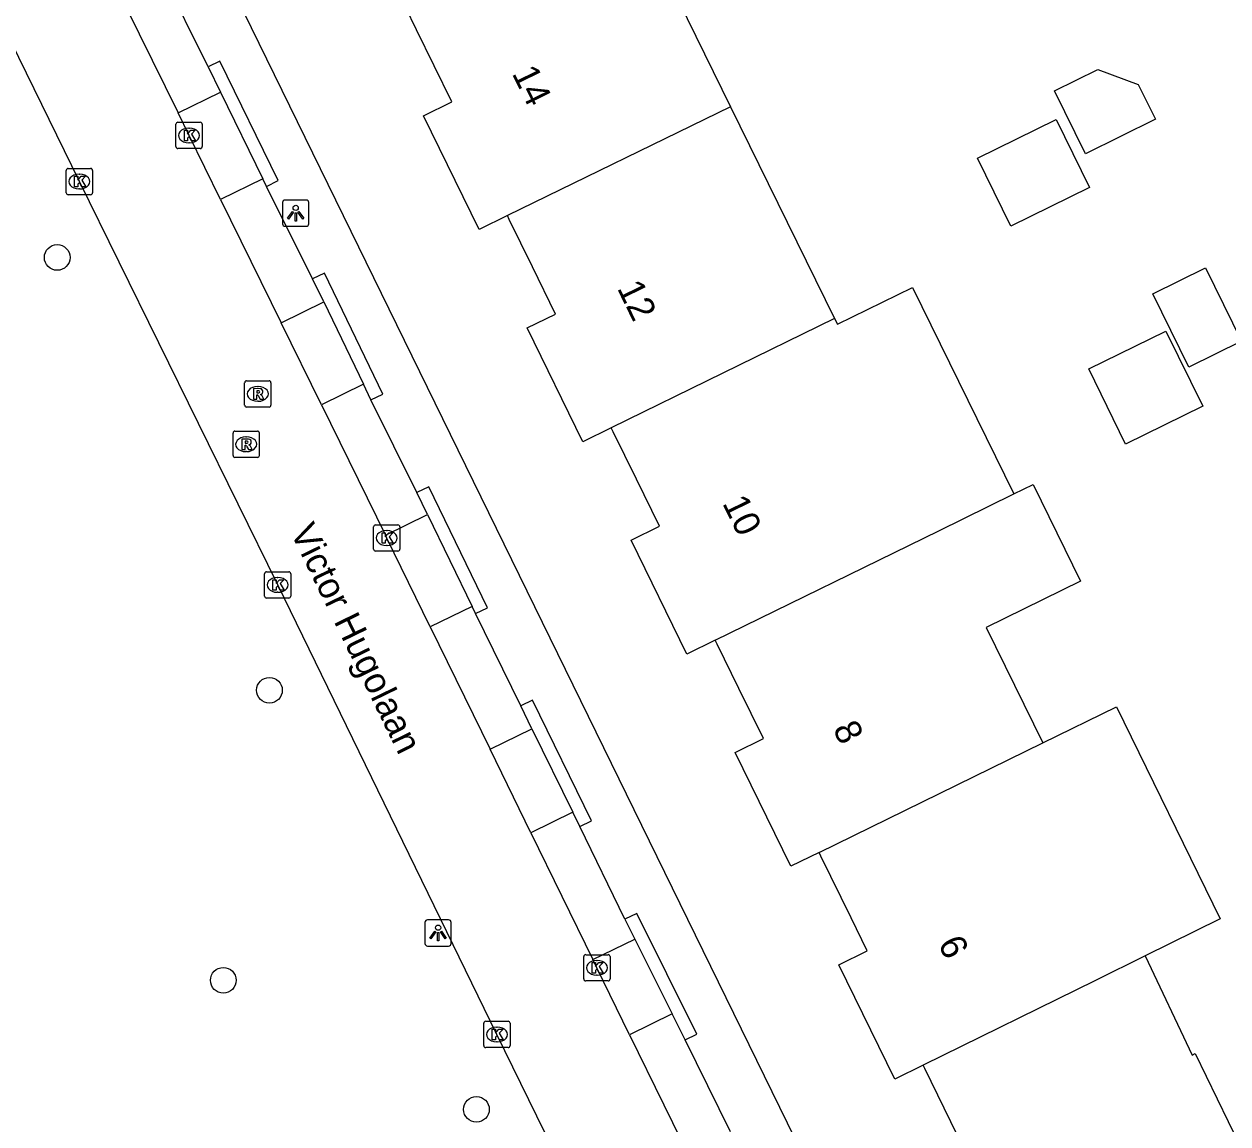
# Model space of a CAD drawing. Extents: x 160457 to 162082, y 388340 to 389736.
# Drawn here: x 160726.81 to 160772.64, y 388685.6 to 388727.48 of the extents above; entities that cross this region are included whole.
import ezdxf

# ---------------------------------------------------------------- set-up
doc = ezdxf.new("R2010")
doc.units = 0
for name, color, linetype in [('IMGEO_Boom', 7, 'Continuous'), ('IMGEO_Kolk', 7, 'Continuous'), ('IMGEO_Lichtpunt', 7, 'Continuous'), ('IMGEO_Openbare_ruimte_label', 7, 'Continuous'), ('IMGEO_Pand', 7, 'Continuous'), ('IMGEO_Pand_nummerreeks', 7, 'Continuous'), ('IMGEO_Parkeervlak_open', 7, 'Continuous'), ('IMGEO_Rijbaan_lokaal_gesloten', 7, 'Continuous'), ('IMGEO_Rioolput', 7, 'Continuous'), ('IMGEO_Voetpad_open', 7, 'Continuous')]:
    doc.layers.add(name, color=color, linetype=linetype)

msp = doc.modelspace()

# ---------------------------------------------------------------- linework, layer by layer
at = {"layer": 'IMGEO_Boom'}
for centre in [(160728.076, 388718.588), (160736.153, 388702.11), (160734.396, 388691.067), (160744.034, 388686.153)]:
    msp.add_circle(centre, 0.489, dxfattribs=at)
at = {"layer": 'IMGEO_Kolk'}
for p, q in [((160732.593, 388722.809), (160732.593, 388723.661)), ((160732.668, 388723.735), (160733.52, 388723.735)), ((160733.081, 388723.515), (160733.106, 388723.515)), ((160733.594, 388723.661), (160733.594, 388722.809)), ((160733.104, 388722.955), (160733.079, 388722.955)), ((160733.52, 388722.735), (160732.668, 388722.735)), ((160728.493, 388721.978), (160729.345, 388721.978)), ((160728.418, 388721.052), (160728.418, 388721.904)), ((160728.906, 388721.758), (160728.931, 388721.758)), ((160729.419, 388721.904), (160729.419, 388721.052)), ((160728.929, 388721.198), (160728.904, 388721.198)), ((160729.345, 388720.978), (160728.493, 388720.978)), ((160740.118, 388707.481), (160740.118, 388708.333)), ((160740.193, 388708.407), (160741.045, 388708.407)), ((160740.606, 388708.187), (160740.631, 388708.187)), ((160741.119, 388708.333), (160741.119, 388707.481)), ((160741.045, 388707.407), (160740.193, 388707.407)), ((160740.629, 388707.627), (160740.604, 388707.627)), ((160735.965, 388705.694), (160735.965, 388706.546)), ((160736.04, 388706.62), (160736.892, 388706.62)), ((160736.453, 388706.4), (160736.478, 388706.4)), ((160736.966, 388706.546), (160736.966, 388705.694)), ((160736.892, 388705.62), (160736.04, 388705.62)), ((160736.476, 388705.84), (160736.451, 388705.84)), ((160748.117, 388691.116), (160748.117, 388691.968)), ((160748.192, 388692.042), (160749.044, 388692.042)), ((160748.605, 388691.822), (160748.63, 388691.822)), ((160749.118, 388691.968), (160749.118, 388691.116)), ((160748.628, 388691.262), (160748.603, 388691.262)), ((160749.044, 388691.042), (160748.192, 388691.042)), ((160744.311, 388688.578), (160744.311, 388689.43)), ((160744.386, 388689.504), (160745.238, 388689.504)), ((160745.312, 388689.43), (160745.312, 388688.578)), ((160744.799, 388689.284), (160744.824, 388689.284)), ((160745.238, 388688.504), (160744.386, 388688.504)), ((160744.822, 388688.724), (160744.797, 388688.724))]:
    msp.add_line(p, q, dxfattribs=at)
for points in [[(160732.593, 388722.809), (160732.593, 388723.661)], [(160732.668, 388723.735), (160733.52, 388723.735)], [(160732.914, 388723.435), (160733.037, 388723.435), (160733.037, 388723.284), (160733.167, 388723.435), (160733.331, 388723.435), (160733.185, 388723.284), (160733.338, 388723.035), (160733.186, 388723.035), (160733.101, 388723.199), (160733.037, 388723.132), (160733.037, 388723.035), (160732.914, 388723.035), (160732.914, 388723.435)], [(160733.594, 388723.661), (160733.594, 388722.809)], [(160733.52, 388722.735), (160732.668, 388722.735)], [(160728.493, 388721.978), (160729.345, 388721.978)], [(160728.418, 388721.052), (160728.418, 388721.904)], [(160728.739, 388721.678), (160728.862, 388721.678), (160728.862, 388721.527), (160728.992, 388721.678), (160729.156, 388721.678), (160729.01, 388721.527), (160729.163, 388721.278), (160729.011, 388721.278), (160728.926, 388721.442), (160728.862, 388721.375), (160728.862, 388721.278), (160728.739, 388721.278), (160728.739, 388721.678)], [(160729.419, 388721.904), (160729.419, 388721.052)], [(160729.345, 388720.978), (160728.493, 388720.978)], [(160740.118, 388707.481), (160740.118, 388708.333)], [(160740.193, 388708.407), (160741.045, 388708.407)], [(160741.119, 388708.333), (160741.119, 388707.481)], [(160740.439, 388708.107), (160740.562, 388708.107), (160740.562, 388707.956), (160740.692, 388708.107), (160740.856, 388708.107), (160740.71, 388707.956), (160740.863, 388707.707), (160740.711, 388707.707), (160740.626, 388707.871), (160740.562, 388707.804), (160740.562, 388707.707), (160740.439, 388707.707), (160740.439, 388708.107)], [(160741.045, 388707.407), (160740.193, 388707.407)], [(160735.965, 388705.694), (160735.965, 388706.546)], [(160736.04, 388706.62), (160736.892, 388706.62)], [(160736.966, 388706.546), (160736.966, 388705.694)], [(160736.286, 388706.32), (160736.409, 388706.32), (160736.409, 388706.169), (160736.539, 388706.32), (160736.703, 388706.32), (160736.557, 388706.169), (160736.71, 388705.92), (160736.558, 388705.92), (160736.473, 388706.084), (160736.409, 388706.017), (160736.409, 388705.92), (160736.286, 388705.92), (160736.286, 388706.32)], [(160736.892, 388705.62), (160736.04, 388705.62)], [(160748.117, 388691.116), (160748.117, 388691.968)], [(160748.192, 388692.042), (160749.044, 388692.042)], [(160748.438, 388691.742), (160748.561, 388691.742), (160748.561, 388691.591), (160748.691, 388691.742), (160748.855, 388691.742), (160748.709, 388691.591), (160748.862, 388691.342), (160748.71, 388691.342), (160748.625, 388691.506), (160748.561, 388691.439), (160748.561, 388691.342), (160748.438, 388691.342), (160748.438, 388691.742)], [(160749.118, 388691.968), (160749.118, 388691.116)], [(160749.044, 388691.042), (160748.192, 388691.042)], [(160744.311, 388688.578), (160744.311, 388689.43)], [(160744.386, 388689.504), (160745.238, 388689.504)], [(160745.312, 388689.43), (160745.312, 388688.578)], [(160744.632, 388689.204), (160744.755, 388689.204), (160744.755, 388689.053), (160744.885, 388689.204), (160745.049, 388689.204), (160744.903, 388689.053), (160745.056, 388688.804), (160744.904, 388688.804), (160744.819, 388688.968), (160744.755, 388688.901), (160744.755, 388688.804), (160744.632, 388688.804), (160744.632, 388689.204)], [(160745.238, 388688.504), (160744.386, 388688.504)]]:
    msp.add_lwpolyline(points, dxfattribs=at)
for centre, start, end in [((160732.67, 388723.659), 91.552, 178.448), ((160732.67, 388723.659), 91.552, 178.448), ((160733.518, 388723.659), 1.552, 88.448), ((160733.518, 388723.659), 1.552, 88.448), ((160732.67, 388722.811), 181.552, 268.448), ((160732.67, 388722.811), 181.552, 268.448), ((160733.518, 388722.811), 271.552, 358.448), ((160733.518, 388722.811), 271.552, 358.448), ((160728.495, 388721.902), 91.552, 178.448), ((160728.495, 388721.902), 91.552, 178.448), ((160729.343, 388721.902), 1.552, 88.448), ((160729.343, 388721.902), 1.552, 88.448), ((160728.495, 388721.054), 181.552, 268.448), ((160728.495, 388721.054), 181.552, 268.448), ((160729.343, 388721.054), 271.552, 358.448), ((160729.343, 388721.054), 271.552, 358.448), ((160740.195, 388708.331), 91.552, 178.448), ((160740.195, 388708.331), 91.552, 178.448), ((160741.043, 388708.331), 1.552, 88.448), ((160741.043, 388708.331), 1.552, 88.448), ((160740.195, 388707.483), 181.552, 268.448), ((160740.195, 388707.483), 181.552, 268.448), ((160741.043, 388707.483), 271.552, 358.448), ((160741.043, 388707.483), 271.552, 358.448), ((160736.042, 388706.544), 91.552, 178.448), ((160736.042, 388706.544), 91.552, 178.448), ((160736.89, 388706.544), 1.552, 88.448), ((160736.89, 388706.544), 1.552, 88.448), ((160736.042, 388705.696), 181.552, 268.448), ((160736.042, 388705.696), 181.552, 268.448), ((160736.89, 388705.696), 271.552, 358.448), ((160736.89, 388705.696), 271.552, 358.448), ((160748.194, 388691.966), 91.552, 178.448), ((160748.194, 388691.966), 91.552, 178.448), ((160749.042, 388691.966), 1.552, 88.448), ((160749.042, 388691.966), 1.552, 88.448), ((160748.194, 388691.118), 181.552, 268.448), ((160748.194, 388691.118), 181.552, 268.448), ((160749.042, 388691.118), 271.552, 358.448), ((160749.042, 388691.118), 271.552, 358.448), ((160744.388, 388689.428), 91.552, 178.448), ((160744.388, 388689.428), 91.552, 178.448), ((160745.236, 388689.428), 1.552, 88.448), ((160745.236, 388689.428), 1.552, 88.448), ((160744.388, 388688.58), 181.552, 268.448), ((160744.388, 388688.58), 181.552, 268.448), ((160745.236, 388688.58), 271.552, 358.448), ((160745.236, 388688.58), 271.552, 358.448)]:
    msp.add_arc(centre, 0.0765, start, end, dxfattribs=at)
for centre, major_axis, ratio, start_param, end_param in [((160733.08, 388723.235), (-0.387, 0.002), 0.722429, 4.712389, 7.853982), ((160733.105, 388723.235), (-0.39, 0.002), 0.717154, 1.570796, 4.712389), ((160728.905, 388721.478), (-0.387, 0.002), 0.722429, 4.712389, 7.853982), ((160728.93, 388721.478), (-0.39, 0.002), 0.717154, 1.570796, 4.712389), ((160740.605, 388707.907), (-0.387, 0.002), 0.722429, 4.712389, 7.853982), ((160740.63, 388707.907), (-0.39, 0.002), 0.717154, 1.570796, 4.712389), ((160736.452, 388706.12), (-0.387, 0.002), 0.722429, 4.712389, 7.853982), ((160736.477, 388706.12), (-0.39, 0.002), 0.717154, 1.570796, 4.712389), ((160748.604, 388691.542), (-0.387, 0.002), 0.722429, 4.712389, 7.853982), ((160748.629, 388691.542), (-0.39, 0.002), 0.717154, 1.570796, 4.712389), ((160744.798, 388689.004), (-0.387, 0.002), 0.722429, 4.712389, 7.853982), ((160744.823, 388689.004), (-0.39, 0.002), 0.717154, 1.570796, 4.712389)]:
    msp.add_ellipse(centre, major_axis=major_axis, ratio=ratio, start_param=start_param, end_param=end_param, dxfattribs=at)
at = {"layer": 'IMGEO_Lichtpunt'}
for p, q in [((160736.654, 388720.678), (160736.654, 388719.871)), ((160736.654, 388720.678), (160736.654, 388719.871)), ((160737.556, 388720.773), (160736.748, 388720.773)), ((160737.556, 388720.773), (160736.748, 388720.773)), ((160737.65, 388719.871), (160737.65, 388720.678)), ((160737.65, 388719.871), (160737.65, 388720.678)), ((160736.748, 388719.777), (160737.556, 388719.777)), ((160736.748, 388719.777), (160737.556, 388719.777)), ((160742.073, 388693.272), (160742.073, 388692.465)), ((160742.073, 388693.272), (160742.073, 388692.465)), ((160742.975, 388693.367), (160742.167, 388693.367)), ((160742.975, 388693.367), (160742.167, 388693.367)), ((160743.069, 388692.465), (160743.069, 388693.272)), ((160743.069, 388692.465), (160743.069, 388693.272)), ((160742.167, 388692.371), (160742.975, 388692.371)), ((160742.167, 388692.371), (160742.975, 388692.371))]:
    msp.add_line(p, q, dxfattribs=at)
for points in [[(160737.028, 388720.342), (160737.067, 388720.314), (160736.879, 388720.052), (160736.841, 388720.079), (160737.028, 388720.342)], [(160737.13, 388720.294), (160737.177, 388720.294), (160737.177, 388719.972), (160737.13, 388719.972), (160737.13, 388720.294)], [(160737.24, 388720.314), (160737.278, 388720.341), (160737.465, 388720.079), (160737.426, 388720.051), (160737.24, 388720.314)], [(160742.447, 388692.936), (160742.486, 388692.908), (160742.298, 388692.646), (160742.26, 388692.673), (160742.447, 388692.936)], [(160742.549, 388692.888), (160742.596, 388692.888), (160742.596, 388692.566), (160742.549, 388692.566), (160742.549, 388692.888)], [(160742.659, 388692.908), (160742.697, 388692.935), (160742.884, 388692.673), (160742.845, 388692.645), (160742.659, 388692.908)]]:
    msp.add_lwpolyline(points, dxfattribs=at)
for centre in [(160737.153, 388720.476), (160742.572, 388693.07)]:
    msp.add_circle(centre, 0.0994, dxfattribs=at)
for centre, start, end in [((160736.748, 388720.678), 90, 180), ((160736.748, 388720.678), 90, 180), ((160737.556, 388720.678), 0, 90), ((160737.556, 388720.678), 0, 90), ((160736.748, 388719.871), 180, 270), ((160736.748, 388719.871), 180, 270), ((160737.556, 388719.871), 270, 0), ((160737.556, 388719.871), 270, 360), ((160742.167, 388693.272), 90, 180), ((160742.167, 388693.272), 90, 180), ((160742.975, 388693.272), 0, 90), ((160742.975, 388693.272), 0, 90), ((160742.167, 388692.465), 180, 270), ((160742.167, 388692.465), 180, 270), ((160742.975, 388692.465), 270, 0), ((160742.975, 388692.465), 270, 360)]:
    msp.add_arc(centre, 0.0946, start, end, dxfattribs=at)
at = {"layer": 'IMGEO_Pand'}
for points in [[(160749.739, 388732.41), (160753.706, 388724.33)], [(160745.21, 388720.181), (160744.132, 388719.655), (160742.013, 388723.984), (160743.091, 388724.511), (160741.751, 388727.256), (160741.332, 388728.115), (160741.257, 388728.268)], [(160769.878, 388723.85), (160767.21, 388722.54), (160766.035, 388724.934), (160767.689, 388725.746), (160769.225, 388725.18), (160769.878, 388723.85)], [(160753.706, 388724.33), (160745.21, 388720.181)], [(160753.706, 388724.33), (160757.667, 388716.261)], [(160767.371, 388721.251), (160764.379, 388719.782), (160763.107, 388722.372), (160766.1, 388723.841), (160767.371, 388721.251)], [(160749.166, 388712.098), (160748.088, 388711.57), (160745.968, 388715.908), (160747.046, 388716.435), (160746.164, 388718.235), (160745.282, 388720.035), (160745.21, 388720.181)], [(160771.154, 388714.418), (160769.785, 388717.209), (160771.783, 388718.189), (160773.152, 388715.398), (160771.154, 388714.418)], [(160757.667, 388716.261), (160757.773, 388716.046), (160760.626, 388717.447), (160764.486, 388709.583)], [(160757.667, 388716.261), (160749.166, 388712.098)], [(160768.743, 388711.485), (160767.34, 388714.344), (160770.275, 388715.784), (160771.678, 388712.925), (160768.743, 388711.485)], [(160753.122, 388704.014), (160752.045, 388703.487), (160749.922, 388707.829), (160751, 388708.356), (160750.12, 388710.152), (160749.239, 388711.948), (160749.166, 388712.098)], [(160753.122, 388704.014), (160761.633, 388708.182), (160764.486, 388709.583)], [(160764.486, 388709.583), (160765.224, 388709.945), (160767.03, 388706.264), (160763.44, 388704.502), (160765.596, 388700.109)], [(160757.075, 388695.936), (160755.997, 388695.408), (160753.88, 388699.743), (160754.959, 388700.27), (160754.025, 388702.173), (160753.193, 388703.87), (160753.122, 388704.014)], [(160765.596, 388700.109), (160768.396, 388701.478), (160772.346, 388693.402), (160769.492, 388691.995)], [(160757.075, 388695.936), (160765.596, 388700.109)], [(160761.039, 388687.829), (160759.963, 388687.299), (160757.831, 388691.661), (160758.909, 388692.188), (160758.294, 388693.446), (160757.145, 388695.793), (160757.075, 388695.936)], [(160769.492, 388691.995), (160767.598, 388691.062), (160761.039, 388687.829)], [(160769.492, 388691.995), (160771.276, 388688.22), (160771.384, 388688.273), (160773.49, 388683.966)], [(160765.001, 388679.757), (160763.926, 388679.224), (160761.785, 388683.575), (160762.861, 388684.104), (160762.335, 388685.179), (160761.1, 388687.705), (160761.039, 388687.829)]]:
    msp.add_lwpolyline(points, dxfattribs=at)
at = {"layer": 'IMGEO_Parkeervlak_open'}
for points in [[(160732.673, 388724.094), (160734.289, 388724.886)], [(160735.898, 388721.585), (160734.291, 388720.796)], [(160736.594, 388716.104), (160738.218, 388716.901)], [(160739.73, 388713.762), (160738.129, 388712.977)], [(160740.565, 388708.014), (160742.172, 388708.803)], [(160743.872, 388705.304), (160742.272, 388704.523)], [(160744.55, 388699.862), (160746.145, 388700.642)], [(160747.699, 388697.462), (160746.104, 388696.682)], [(160748.464, 388691.854), (160750.063, 388692.635)], [(160751.48, 388689.787), (160749.864, 388688.996)]]:
    msp.add_lwpolyline(points, dxfattribs=at)
at = {"layer": 'IMGEO_Rijbaan_lokaal_gesloten'}
for points in [[(160761.961, 388654.06), (160761.131, 388655.754), (160751.828, 388674.672), (160744.813, 388689.005), (160736.467, 388706.121), (160728.92, 388721.478), (160721.425, 388736.799), (160714.944, 388750), (160712.441, 388755.098), (160704.23, 388771.946), (160697.898, 388784.974), (160695.603, 388789.801)], [(160730.208, 388729.122), (160732.673, 388724.094)], [(160734.291, 388720.796), (160733.094, 388723.235), (160732.673, 388724.094)], [(160734.291, 388720.796), (160736.594, 388716.104)], [(160738.129, 388712.977), (160736.594, 388716.104)], [(160738.129, 388712.977), (160740.565, 388708.014)], [(160742.272, 388704.523), (160740.618, 388707.906), (160740.565, 388708.014)], [(160742.272, 388704.523), (160744.55, 388699.862)], [(160746.104, 388696.682), (160744.55, 388699.862)], [(160746.104, 388696.682), (160748.464, 388691.854)], [(160749.864, 388688.996), (160748.617, 388691.542), (160748.464, 388691.854)], [(160749.864, 388688.996), (160752.476, 388683.661)]]:
    msp.add_lwpolyline(points, dxfattribs=at)
at = {"layer": 'IMGEO_Rioolput'}
for p, q in [((160735.21, 388712.968), (160735.21, 388713.82)), ((160735.285, 388713.894), (160736.137, 388713.894)), ((160736.211, 388713.82), (160736.211, 388712.968)), ((160735.698, 388713.674), (160735.723, 388713.674)), ((160736.137, 388712.894), (160735.285, 388712.894)), ((160735.721, 388713.114), (160735.696, 388713.114)), ((160734.767, 388711.05), (160734.767, 388711.902)), ((160734.842, 388711.976), (160735.694, 388711.976)), ((160735.768, 388711.902), (160735.768, 388711.05)), ((160735.255, 388711.756), (160735.28, 388711.756)), ((160735.694, 388710.976), (160734.842, 388710.976)), ((160735.278, 388711.196), (160735.253, 388711.196))]:
    msp.add_line(p, q, dxfattribs=at)
for points in [[(160735.21, 388712.968), (160735.21, 388713.82)], [(160735.285, 388713.894), (160736.137, 388713.894)], [(160736.211, 388713.82), (160736.211, 388712.968)], [(160735.799, 388713.592), (160735.547, 388713.594), (160735.547, 388713.194)], [(160735.547, 388713.194), (160735.671, 388713.194), (160735.671, 388713.356), (160735.682, 388713.356)], [(160735.725, 388713.513), (160735.671, 388713.513), (160735.671, 388713.432)], [(160735.671, 388713.432), (160735.723, 388713.432)], [(160735.729, 388713.327), (160735.8, 388713.194), (160735.94, 388713.194), (160735.875, 388713.32)], [(160736.137, 388712.894), (160735.285, 388712.894)], [(160734.767, 388711.05), (160734.767, 388711.902)], [(160734.842, 388711.976), (160735.694, 388711.976)], [(160735.768, 388711.902), (160735.768, 388711.05)], [(160735.356, 388711.674), (160735.104, 388711.676), (160735.104, 388711.276)], [(160735.104, 388711.276), (160735.228, 388711.276), (160735.228, 388711.438), (160735.239, 388711.438)], [(160735.282, 388711.595), (160735.228, 388711.595), (160735.228, 388711.514)], [(160735.228, 388711.514), (160735.28, 388711.514)], [(160735.286, 388711.409), (160735.357, 388711.276), (160735.497, 388711.276), (160735.432, 388711.402)], [(160735.694, 388710.976), (160734.842, 388710.976)]]:
    msp.add_lwpolyline(points, dxfattribs=at)
for centre, radius, start, end in [((160735.287, 388713.818), 0.0765, 91.552, 178.448), ((160735.287, 388713.818), 0.0765, 91.552, 178.448), ((160736.135, 388713.818), 0.0765, 1.552, 88.448), ((160736.135, 388713.818), 0.0765, 1.552, 88.448), ((160735.681, 388713.303), 0.0533, 26.0293, 88.6989), ((160735.707, 388713.621), 0.19, 274.7715, 282.9687), ((160735.731, 388713.417), 0.0964, 77.0061, 93.1865), ((160735.745, 388713.474), 0.0378, 276.6634, 79.6772), ((160735.798, 388713.482), 0.109, 350.3612, 89.416), ((160735.796, 388713.482), 0.112, 277.5842, 350.9817), ((160735.78, 388713.267), 0.108, 29.5134, 73.7905), ((160735.287, 388712.97), 0.0765, 181.552, 268.448), ((160735.287, 388712.97), 0.0765, 181.552, 268.448), ((160736.135, 388712.97), 0.0765, 271.552, 358.448), ((160736.135, 388712.97), 0.0765, 271.552, 358.448), ((160734.844, 388711.9), 0.0765, 91.552, 178.448), ((160734.844, 388711.9), 0.0765, 91.552, 178.448), ((160735.692, 388711.9), 0.0765, 1.552, 88.448), ((160735.692, 388711.9), 0.0765, 1.552, 88.448), ((160735.238, 388711.385), 0.0533, 26.0293, 88.6989), ((160735.264, 388711.703), 0.19, 274.7715, 282.9687), ((160735.288, 388711.499), 0.0964, 77.0061, 93.1865), ((160735.302, 388711.556), 0.0378, 276.6634, 79.6772), ((160735.355, 388711.564), 0.109, 350.3612, 89.416), ((160735.353, 388711.564), 0.112, 277.5842, 350.9817), ((160735.337, 388711.349), 0.108, 29.5134, 73.7905), ((160734.844, 388711.052), 0.0765, 181.552, 268.448), ((160734.844, 388711.052), 0.0765, 181.552, 268.448), ((160735.692, 388711.052), 0.0765, 271.552, 358.448), ((160735.692, 388711.052), 0.0765, 271.552, 358.448)]:
    msp.add_arc(centre, radius, start, end, dxfattribs=at)
for centre, major_axis, ratio, start_param, end_param in [((160735.697, 388713.394), (-0.387, 0.002), 0.722429, 4.712389, 7.853982), ((160735.722, 388713.394), (-0.39, 0.002), 0.717154, 1.570796, 4.712389), ((160735.254, 388711.476), (-0.387, 0.002), 0.722429, 4.712389, 7.853982), ((160735.279, 388711.476), (-0.39, 0.002), 0.717154, 1.570796, 4.712389)]:
    msp.add_ellipse(centre, major_axis=major_axis, ratio=ratio, start_param=start_param, end_param=end_param, dxfattribs=at)
at = {"layer": 'IMGEO_Voetpad_open'}
for points in [[(160703.918, 388791.781), (160724.364, 388750), (160764.9, 388667.168), (160765.381, 388666.169), (160766.298, 388664.267)], [(160733.82, 388725.848), (160732.062, 388729.416)], [(160736.039, 388721.297), (160736.488, 388721.516), (160734.269, 388726.067), (160733.82, 388725.848)], [(160733.82, 388725.848), (160734.289, 388724.886)], [(160734.289, 388724.886), (160735.898, 388721.585)], [(160736.039, 388721.297), (160735.898, 388721.585)], [(160737.796, 388717.777), (160736.039, 388721.297)], [(160740.016, 388713.168), (160740.466, 388713.384), (160738.246, 388717.993), (160737.796, 388717.777)], [(160738.218, 388716.901), (160737.796, 388717.777)], [(160738.218, 388716.901), (160739.73, 388713.762)], [(160740.016, 388713.168), (160739.73, 388713.762)], [(160741.767, 388709.638), (160740.016, 388713.168)], [(160744.002, 388705.036), (160744.451, 388705.254), (160742.216, 388709.856), (160741.767, 388709.638)], [(160742.172, 388708.803), (160741.767, 388709.638)], [(160742.172, 388708.803), (160743.872, 388705.304)], [(160744.002, 388705.036), (160743.872, 388705.304)], [(160745.719, 388701.513), (160744.002, 388705.036)], [(160747.964, 388696.92), (160748.413, 388697.139), (160746.168, 388701.732), (160745.719, 388701.513)], [(160746.145, 388700.642), (160745.719, 388701.513)], [(160746.145, 388700.642), (160747.699, 388697.462)], [(160747.964, 388696.92), (160747.699, 388697.462)], [(160749.687, 388693.39), (160747.964, 388696.92)], [(160751.973, 388688.796), (160752.42, 388689.018), (160750.134, 388693.612), (160749.687, 388693.39)], [(160749.687, 388693.39), (160750.063, 388692.635)], [(160750.063, 388692.635), (160751.48, 388689.787)], [(160751.973, 388688.796), (160751.48, 388689.787)], [(160753.709, 388685.3), (160751.973, 388688.796)]]:
    msp.add_lwpolyline(points, dxfattribs=at)

# ---------------------------------------------------------------- texts
at = {"layer": 'IMGEO_Openbare_ruimte_label'}
msp.add_text('Victor Hugolaan', height=1, rotation=295.9757, dxfattribs=at).set_placement((160736.928, 388708.154))
at = {"layer": 'IMGEO_Pand_nummerreeks'}
for s, p in [('14', (160745.37, 388725.601)), ('12', (160749.372, 388717.423)), ('10', (160753.379, 388709.236)), ('8', (160757.583, 388700.64)), ('6', (160761.585, 388692.463))]:
    msp.add_text(s, height=1, rotation=296.0751, dxfattribs=at).set_placement(p)

doc.saveas('drawing.dxf')
